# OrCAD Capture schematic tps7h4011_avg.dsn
size Custom
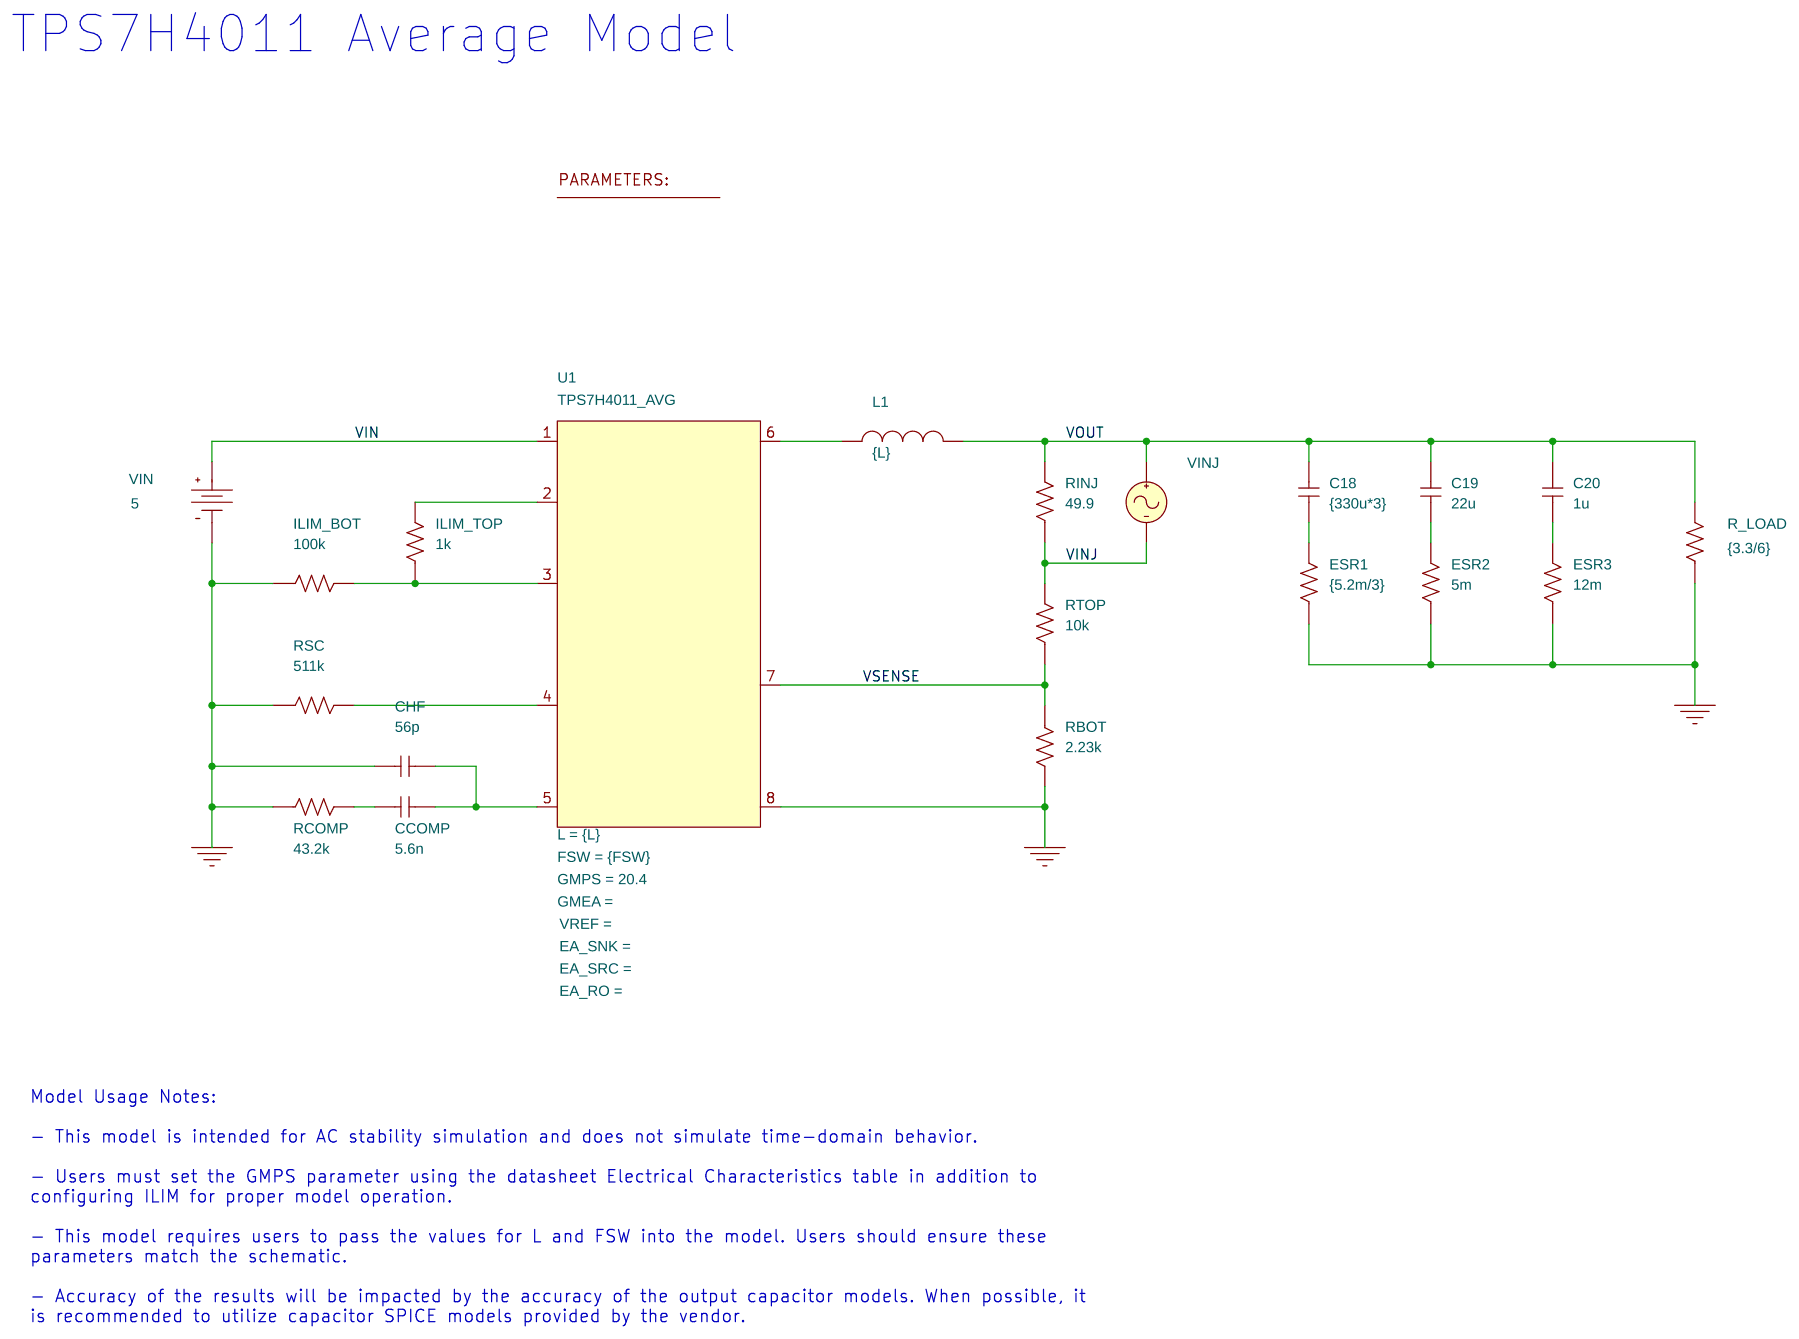
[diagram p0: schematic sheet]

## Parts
1  PARAM
C18  {330u*3}  [RAD/CK05]
C19  22u  [RAD/CK05]
C20  1u  [RAD/CK05]
CCOMP  5.6n  [RAD/CK05]
CHF  56p  [RAD/CK05]
ESR1  {5.2m/3}  [AXRC05]
ESR2  5m  [AXRC05]
ESR3  12m  [AXRC05]
ILIM_BOT  100k  [AX/RC05]
ILIM_TOP  1k  [AX/RC05]
L1  {L}  [DISC/.350x.175/LS.200x.100/.034]
R_LOAD  {3.3/6}  [AX/RC05]
RBOT  2.23k  [AX/RC05]
RCOMP  43.2k  [AX/RC05]
RINJ  49.9  [AX/RC05]
RSC  511k  [AX/RC05]
RTOP  10k  [AX/RC05]
U1  TPS7H4011_AVG
VIN  VDC
VINJ  VAC

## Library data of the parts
1 = PARAM: FSW: 500k; L: 2.2u
C18-C20 CCOMP CHF = C
ESR1-ESR3 ILIM_BOT ILIM_TOP R_LOAD RBOT RCOMP RINJ RSC RTOP = R
L1 = L_v2
U1 = TPS7H4011_AVG: FSW: {FSW}; GMPS: 20.4; L: {L}
VIN = VDC: DC: 5
VINJ = VAC

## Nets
VIN: U1.1(VIN) VIN.0(+)
VINJ: RINJ.1 RTOP.2 VINJ.2(-)
0: CHF.2 ESR1.1 ESR2.1 ESR3.1 ILIM_BOT.1 R_LOAD.1 RBOT.2 RCOMP.1 RSC.1 U1.8(GND) VIN.1(-)
VOUT: C18.1 C19.1 C20.1 L1.2 R_LOAD.2 RINJ.2 VINJ.1(+)
VSENSE: RBOT.1 RTOP.1 U1.7(VSENSE)
N16759756: CCOMP.1 CHF.1 U1.5(COMP)
N16759812: CCOMP.2 RCOMP.2
N16759862: RSC.2 U1.4(RSC)
N16763547: L1.1 U1.6(SW)
N16763858: C18.2 ESR1.2
N16763864: C19.2 ESR2.2
N16763870: C20.2 ESR3.2
N16767435: ILIM_TOP.2 U1.2(LDOCAP)
N16767439: ILIM_BOT.2 ILIM_TOP.1 U1.3(ILIM)

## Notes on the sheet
- TPS7H4011 Average Model
- Model Usage Notes:
  - This model is intended for AC stability simulation and does not simulate time-domain behavior.
  - Users must set the GMPS parameter using the datasheet Electrical Characteristics table in addition to
  configuring ILIM for proper model operation.
  - This model requires users to pass the values for L and FSW into the model. Users should ensure these
  parameters match the schematic.
  - Accuracy of the results will be impacted by the accuracy of the output capacitor models. When possible, it
  is recommended to utilize capacitor SPICE models provided by the vendor.
